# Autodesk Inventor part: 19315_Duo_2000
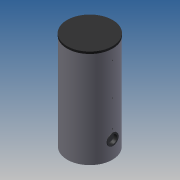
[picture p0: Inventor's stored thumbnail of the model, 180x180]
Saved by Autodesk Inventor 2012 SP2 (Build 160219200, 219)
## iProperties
allow_slope_adjustment: 0 ul
connection_type: 13 ul
flow_configuration2: 1 ul
flow_direction: 2 ul
loss_method: 0 ul
radius: 28,500 mm
radius: 12,250 mm
radius: 9,500 mm
description: 0:0:19316_Duo_2000
manufacturer: 0:0:Flamco Group
model: 0:0:Duo 2000
url: 0:0:www.flamcogroup.com
radius: 15,375 mm
Created: 2014-05
Part Number: 19315_Duo_2000
Material: Default
Document SubType Name: Modeling
Designer: michel
Density: 1 g/cm^3
Author: michel
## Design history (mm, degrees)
sketch "Sketch1"
  geometry: C1 r 550 at (0, 0); 1 further point
  constraints: 1 centre point, 1 coincident
  dimensions: "d0" = 1100 diameter of C1
extrude "Extrusion1" new body sketch "Sketch1" distance "d1" = 2400; taper "d2" = 0 deg
sketch "Sketch2"
  geometry: L1 (-550, 2400)-(550, 2400) reference; L2 (-550, 0)-(550, 0) reference; L3 (550, 0)-(550, 2400) reference; L4 (550, 2400)-(555, 2400); L5 (555, 2400)-(555, 2350); L6 (555, 2350)-(550, 2350); L7 (550, 2350)-(550, 2400); L8 (0, -464)-(0, 2784) reference; 1 further point
  constraints: 8 end point, 2 parallel, 1 horizontal, 1 perpendicular
  dimensions: "d3" = 5 distance of L5.end L6.end; "d4" = 50 distance of L4.end L5.end
revolve "Revolution1" sketch "Sketch2" stored, may be unused: angle "d5" = 90 deg
workplane "Work Plane1"
workplane "Work Plane2"
workplane "Work Plane3"
workplane "Work Plane4"
workplane "Work Plane5"
workplane "Work Plane6"
workplane "Work Plane11"
workplane "Work Plane12"
workplane "Work Plane13"
sketch "Sketch3"
  geometry: L1 (771.4, 2255)-(-771.4, 2255) reference; L2 (771.4, 1755)-(-771.4, 1755) reference; L3 (771.4, 1575)-(-771.4, 1575) reference; L4 (771.4, 455)-(-771.4, 455) reference; L5 (771.4, 105)-(-771.4, 105) reference; L6 (550, 0)-(550, 2350) reference; L7 (550, 2255)-(510, 2255); L8 (510, 2255)-(510, 2284.805); L9 (510, 2284.805)-(550, 2284.805); L10 (550, 1755)-(510, 1755); L11 (510, 1755)-(510, 1771.625); L12 (510, 1771.625)-(550, 1771.625); L13 (550, 1771.625)-(550, 1755); L14 (335, 2226.5)-(335, 2225.195); L15 (335, 2225.195)-(551, 2225.195); L16 (551, 2225.195)-(551, 2226.5); L17 (551, 2226.5)-(335, 2226.5); L18 (510, 1575)-(510, 1604.805); L19 (550, 1575)-(510, 1575); L20 (510, 1604.805)-(550, 1604.805); L21 (550, 1604.805)-(550, 1575); L22 (335, 1546.5)-(335, 1545.195); L23 (335, 1545.195)-(551, 1545.195); L24 (551, 1545.195)-(551, 1546.5); L25 (551, 1546.5)-(335, 1546.5); L26 (510, 484.805)-(550, 484.805); L27 (510, 455)-(510, 484.805); L28 (550, 455)-(510, 455); L29 (550, 484.805)-(550, 455); L30 (551, 426.5)-(335.165, 426.5); L31 (335.165, 426.5)-(335.165, 425.195); L32 (335.165, 425.195)-(551, 425.195); L33 (551, 425.195)-(551, 426.5); L34 (510, 134.805)-(550, 134.805); L35 (510, 105)-(510, 134.805); L36 (550, 105)-(510, 105); L37 (550, 134.805)-(550, 105); L38 (551, 76.5)-(335, 76.5); L39 (335, 76.5)-(335, 75.195); L40 (335, 75.195)-(551, 75.195); L41 (551, 75.195)-(551, 76.5); L42 (335, 1739.625)-(335, 1738.375); L43 (551, 1738.375)-(551, 1739.625); L44 (551, 1739.625)-(335, 1739.625); L45 (-777, 2100)-(777, 2100) reference; L46 (771.4, 1300)-(-771.4, 1300) reference; L47 (-550, 0)-(-550, 2350) reference; L48 (-550, 2100)-(-510, 2100); L49 (-510, 2100)-(-510, 2110.475); L50 (-510, 2110.475)-(-550, 2110.475); L51 (-550, 2110.475)-(-550, 2100); L52 (-551, 2089.525)-(-335, 2089.525); L53 (-335, 2089.525)-(-335, 2090.5); L54 (-335, 2090.5)-(-551, 2090.5); L55 (-551, 2090.5)-(-551, 2089.525); L56 (-550, 1300)-(-335, 1300); L57 (-335, 1300)-(-335, 1313.22); L58 (-335, 1313.22)-(-550, 1313.22); L59 (-550, 1313.22)-(-550, 1300); L60 (-551, 1286.78)-(-335, 1286.78); L61 (-335, 1286.78)-(-335, 1287.75); L62 (-335, 1287.75)-(-551, 1287.75); L63 (-551, 1287.75)-(-551, 1286.78); L64 (550, 2284.805)-(550, 2255)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; 2 further points
  constraints: 128 end point, 20 parallel, 9 horizontal, 9 perpendicular, 8 point on line, 1 collinear
  dimensions: "d19" = 40 distance of L8.end L9.end; "d21" = 40 distance of L11.end L12.end; "d70" = 29.805 distance between parallel lines of L1 L9; "d73" = 40 distance of L18.end L20.end; "d74" = 40 distance of L26.start L26.end; "d75" = 40 distance of L34.start L34.end; "d76" = 29.805 distance between parallel lines of L3 L20; "d85" = 16.625 distance between parallel lines of L2 L12; "d108" = 29.805 distance between parallel lines of L1 L15 (derived); "d109" = 1.305 distance between parallel lines of L17 L15 (derived); "d110" = 16.625 distance between parallel lines of L10 L12 (= d85); "d113" = 29.805 distance between parallel lines of L19 L20 (= d76); "d114" = 29.805 distance between parallel lines of L23 L3 (derived); "d115" = 1.305 distance between parallel lines of L25 L23 (derived); "d116" = 29.805 distance between parallel lines of L4 L26; "d117" = 29.805 distance of L26.start L27.start (= d116); "d118" = 29.805 distance between parallel lines of L32 L4 (derived); "d119" = 1.305 distance between parallel lines of L30 L32 (derived); "d120" = 29.805 distance from line of L34 L35.start (= d121); "d121" = 29.805 distance between parallel lines of L5 L34; "d122" = 29.805 distance between parallel lines of L40 L5 (derived); "d123" = 1.305 distance between parallel lines of L38 L40 (derived); "d129" = 40 distance of L50.end L49.end; "d130" = 10.475 distance of L49.end L48.end; "d131" = 10.475 distance between parallel lines of L45 L52; "d132" = 0.975 distance between parallel lines of L54 L52; "d134" = 13.22 distance between parallel lines of L46 L58; "d135" = 13.22 distance between parallel lines of L46 L60 (derived); "d136" = 0.97 distance between parallel lines of L62 L60 (derived); "d154" = 1 distance between parallel lines of L47 L55; "d155" = 1 distance between parallel lines of L47 L63; "d157" = 1 distance between parallel lines of L6 L16; "d158" = 0 distance between parallel lines of L6 L13; "d159" = 1 distance between parallel lines of L6 L43; "d160" = 0 distance between parallel lines of L6 L21; "d161" = 1 distance between parallel lines of L6 L24; "d162" = 0 distance between parallel lines of L6 L29; "d163" = 1 distance between parallel lines of L6 L33; "d164" = 0 distance between parallel lines of L6 L37; "d165" = 1 distance between parallel lines of L6 L41; "d166" = 16.625 distance between parallel lines of L65 L2 (derived); "d167" = 1.25 distance between parallel lines of L44 L65 (derived); "d173" = 0 distance between parallel lines of L6 L64; "d181" = 40 distance of L69.end L68.end; "d182" = 13.22 distance of L68.end L67.end; "d183" = 13.22 distance between parallel lines of L66 L73 (derived); "d184" = 0.97 distance between parallel lines of L71 L73 (derived); "d185" = 1 distance between parallel lines of L47 L74
revolve "Revolution2" stored, may be unused: angle "d23" = 90 deg
sketch "Sketch5"
  geometry: L1 (-550, 0)-(-550, 2350) reference; L2 (-550, 0)-(-550, 435); L3 (-220, 435)-(-594, 435); L4 (-550, 435)-(-562.5, 435); L5 (-562.5, 435)-(-562.5, 575); L6 (-562.5, 575)-(-550, 575); L7 (-550, 575)-(-550, 435); L8 (-550, 0)-(550, 0) reference; 1 further point
  constraints: 12 end point, 2 parallel, 2 perpendicular, 1 horizontal, 1 point on line
  dimensions: "d35" = 435 distance of L1.start L2.end; "d36" = 12.5 distance of L5.end L6.end; "d37" = 140 distance of L4.end L5.end; "d124" = 435 distance between parallel lines of L8 L3 (= d35)
revolve "Revolution7" sketch "Sketch5" stored, may be unused: angle "d38" = 90 deg
sketch "Sketch6"
  geometry: C1 r 122.5 at (0, 0); A1 r 140 centre (0, 0) between (140, 0) and (-140, 0) reference; 1 further point
  constraints: 1 centre point, 1 coincident
  dimensions: "d39" = 245 diameter of C1
extrude "Extrusion3" join sketch "Sketch6" stored distance "d40" = 40; taper "d41" = 0 deg
sketch "Sketch7"
  geometry: C1 r 140 at (0, 0) reference; C2 r 102.5 at (0, 0); 1 further point
  constraints: 1 centre point, 1 coincident
  dimensions: "d42" = 205 diameter of C2
extrude "Extrusion4" cut sketch "Sketch7" distance "d43" = 80; taper "d44" = 0 deg
revolve "Revolution9" stored, may be unused: angle "d69" = 90 deg
revolve "Revolution10" stored, may be unused: angle "d92" = 90 deg
revolve "Revolution11" stored, may be unused: angle "d93" = 90 deg
revolve "Revolution12" stored, may be unused: angle "d94" = 90 deg
revolve "Revolution13" stored, may be unused: angle "d95" = 90 deg
revolve "Revolution14" stored, may be unused: angle "d96" = 90 deg
revolve "Revolution15" stored, may be unused: angle "d97" = 90 deg
revolve "Revolution16" stored, may be unused: angle "d98" = 90 deg
revolve "Revolution17" stored, may be unused: angle "d99" = 90 deg
revolve "Revolution18" stored, may be unused: angle "d138" = 90 deg
revolve "Revolution19" stored, may be unused: angle "d139" = 90 deg
revolve "Revolution20" stored, may be unused: angle "d140" = 90 deg
revolve "Revolution21" stored, may be unused: angle "d141" = 90 deg
revolve "Revolution22" stored, may be unused: angle "d186" = 90 deg
revolve "Revolution23" stored, may be unused: angle "d187" = 90 deg
body "Solid1"
node "Projected Loop1"
other parameters: "d12" = 0, "d188" = -2255, "d189" = -1755, "d190" = -1575, "d191" = -455, "d192" = -105
